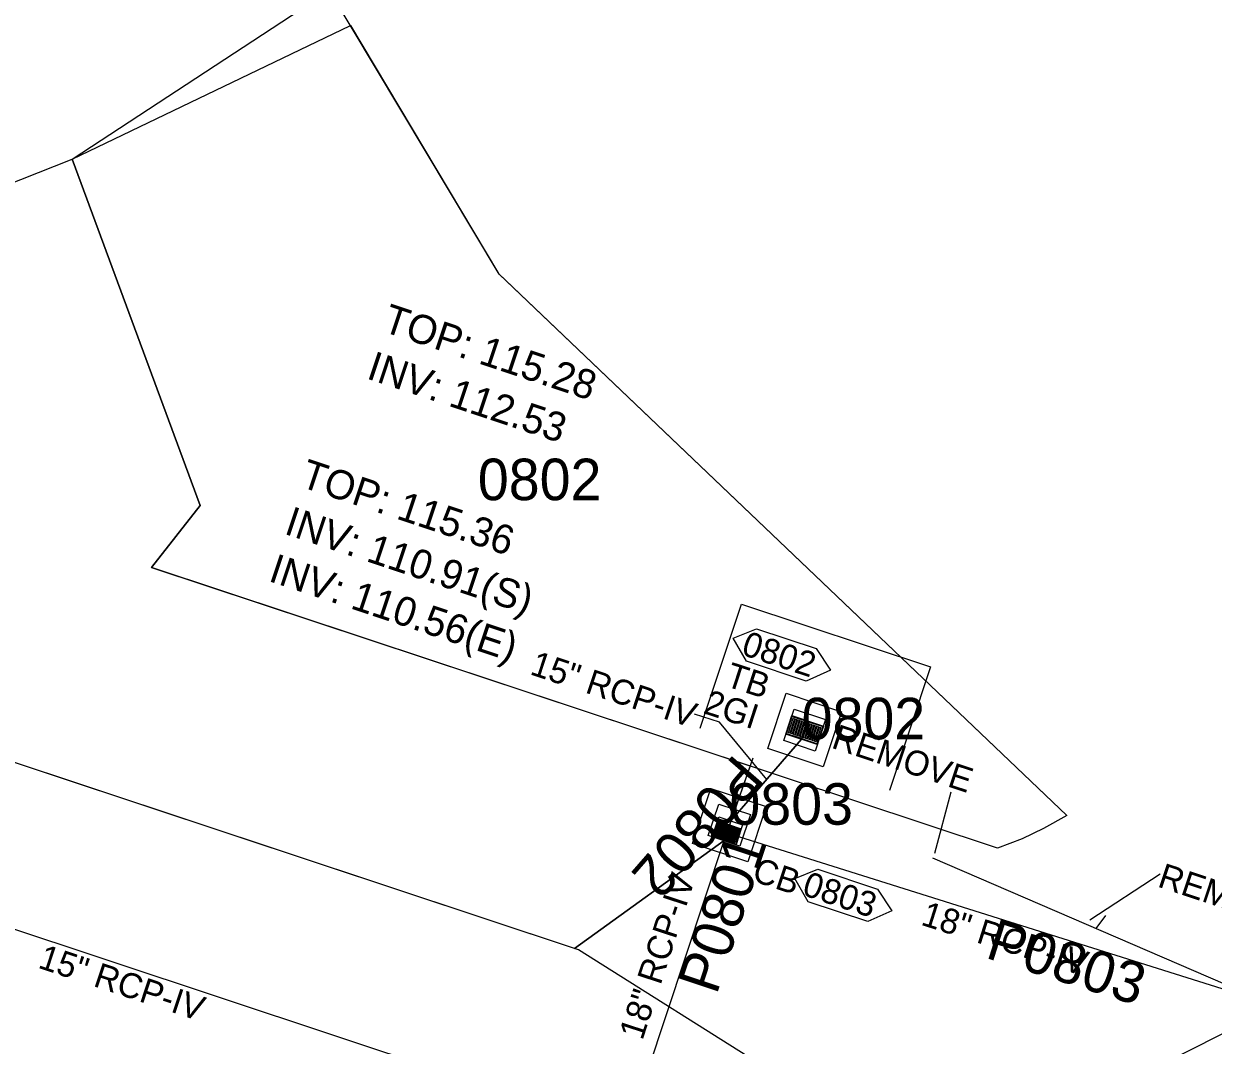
# Model space of a CAD drawing. Extents: x 2296558 to 2299313, y 599200 to 601383.
# Drawn here: x 2298959.5 to 2299102.6, y 599495.2 to 599618.1 of the extents above; entities that cross this region are included whole.
import ezdxf

# ---------------------------------------------------------------- set-up
doc = ezdxf.new("R2010")
doc.units = 0
for name, color, linetype in [('Prop Drainage Structure Box Number Symbol CELL', 7, 'Continuous'), ('Prop Drainage Structure Catch Basin Grate 840 03F Label', 7, 'Continuous'), ('Prop Drainage Structure Catch Basin Grate 840 03G CELL', 7, 'Continuous'), ('Prop Drainage Structure Catch Basin Grate 840 03G Label', 7, 'Continuous'), ('Prop Drainage Structure Drop Inlet Grate 2 Narrow Slots and Sag Grates 840 24 TB CELL', 7, 'Continuous'), ('Prop Drainage Structure Drop Inlet Grate 2 Narrow Slots and Sag Grates 840 24 TB Label', 7, 'Continuous'), ('Prop Drainage Structure Pipe RCP 15in Class IV', 7, 'Continuous'), ('Prop Drainage Structure Pipe RCP 15in Class IV Label', 7, 'Continuous'), ('Prop Drainage Structure Pipe RCP 18in Class IV', 7, 'Continuous'), ('Prop Drainage Structure Pipe RCP 18in Class IV Label', 7, 'Continuous'), ('Prop Drainage Structure Pipe Removal', 7, 'Continuous'), ('Prop Drainage Structure Plot Symbol 20 Scale', 7, 'Continuous'), ('Prop Drainage Structure Plot Symbol 50 Scale', 7, 'Continuous'), ('Prop Drainage Structure Removal Label', 7, 'Continuous'), ('Prop Drainage Structure Tops and Inverts LABEL', 7, 'Continuous'), ('Prop Plan Preparation Watershed Post Construction', 7, 'Continuous'), ('Scratch_Level_1', 7, 'Continuous'), ('Scratch_Level_3', 7, 'Continuous'), ('Scratch_Level_5', 7, 'Continuous'), ('Scratch_Level_9', 7, 'Continuous')]:
    doc.layers.add(name, color=color, linetype=linetype)

msp = doc.modelspace()

# ---------------------------------------------------------------- linework, layer by layer
at = {"layer": 'Prop Drainage Structure Box Number Symbol CELL'}
for points in [[(2299047.65, 599545.31), (2299054.83, 599542.93), (2299056.55, 599540.31), (2299053.63, 599539.02), (2299046.45, 599541.4), (2299044.85, 599544.19), (2299047.65, 599545.31)], [(2299055.05, 599516.36), (2299062.23, 599513.98), (2299063.95, 599511.36), (2299061.03, 599510.07), (2299053.85, 599512.45), (2299052.25, 599515.24), (2299055.05, 599516.36)]]:
    msp.add_lwpolyline(points, dxfattribs=at)
at = {"layer": 'Prop Drainage Structure Catch Basin Grate 840 03G CELL'}
for p, q in [((2299042.64, 599521.2), (2299042.64, 599521.2)), ((2299044.17, 599521.25), (2299042.67, 599520.52)), ((2299044.25, 599521.51), (2299042.76, 599520.79)), ((2299043.98, 599521.6), (2299042.85, 599521.05)), ((2299043.71, 599521.69), (2299042.93, 599521.31)), ((2299043.44, 599521.78), (2299043.02, 599521.57)), ((2299043.05, 599521.95), (2299043.12, 599521.98)), ((2299043.17, 599521.87), (2299043.11, 599521.84)), ((2299044.55, 599522.19), (2299044.55, 599522.19)), ((2299044.09, 599520.99), (2299042.72, 599520.33)), ((2299044, 599520.73), (2299042.99, 599520.24)), ((2299043.91, 599520.47), (2299043.26, 599520.15)), ((2299043.83, 599520.2), (2299043.53, 599520.06)), ((2299043.77, 599519.83), (2299043.77, 599519.83)), ((2299044.01, 599519.99), (2299045.37, 599520.65)), ((2299044.06, 599520.73), (2299044.06, 599520.73)), ((2299045.42, 599520.54), (2299044.06, 599519.88)), ((2299044.28, 599519.9), (2299045.28, 599520.39)), ((2299045.33, 599520.28), (2299044.33, 599519.79)), ((2299044.55, 599519.81), (2299045.19, 599520.13)), ((2299045.25, 599520.01), (2299044.6, 599519.7)), ((2299044.82, 599519.72), (2299045.1, 599519.86)), ((2299045.16, 599519.75), (2299044.87, 599519.61)), ((2299045.49, 599520.29), (2299045.49, 599520.29))]:
    msp.add_line(p, q, dxfattribs=at)
for points in [[(2299042.97, 599522.19), (2299045.82, 599521.24), (2299045.19, 599519.35), (2299042.34, 599520.29), (2299043.13, 599522.66), (2299045.97, 599521.72), (2299045.82, 599521.24)], [(2299042.98, 599522.18), (2299045.8, 599521.24), (2299045.18, 599519.36), (2299042.35, 599520.3), (2299042.98, 599522.18)], [(2299045.1, 599519.52), (2299042.51, 599520.38), (2299043.06, 599522.02), (2299045.65, 599521.16), (2299045.1, 599519.52)], [(2299042.62, 599520.64), (2299044.23, 599521.42), (2299044.17, 599521.25)], [(2299042.7, 599520.9), (2299044.19, 599521.62), (2299044.25, 599521.51)], [(2299042.79, 599521.16), (2299043.92, 599521.71), (2299043.98, 599521.6)], [(2299042.88, 599521.42), (2299043.65, 599521.8), (2299043.71, 599521.69)], [(2299042.97, 599521.69), (2299043.38, 599521.89), (2299043.44, 599521.78)], [(2299045.32, 599521.15), (2299044.07, 599520.54), (2299044.12, 599520.71), (2299045.27, 599521.26)], [(2299045.05, 599521.24), (2299044.16, 599520.8), (2299044.21, 599520.97), (2299045, 599521.35)], [(2299044.78, 599521.33), (2299044.24, 599521.07), (2299044.3, 599521.23), (2299044.73, 599521.44)], [(2299044.52, 599521.42), (2299044.33, 599521.33), (2299044.39, 599521.5), (2299044.46, 599521.53)], [(2299042.66, 599520.44), (2299044.14, 599521.16), (2299044.09, 599520.99)], [(2299042.93, 599520.35), (2299044.05, 599520.89), (2299044, 599520.73)], [(2299043.2, 599520.26), (2299043.97, 599520.63), (2299043.91, 599520.47)], [(2299043.47, 599520.17), (2299043.88, 599520.37), (2299043.83, 599520.2)], [(2299045.51, 599520.8), (2299043.9, 599520.02), (2299043.95, 599520.18), (2299045.45, 599520.91)], [(2299045.59, 599521.06), (2299043.98, 599520.28), (2299044.04, 599520.45), (2299045.54, 599521.18)]]:
    msp.add_lwpolyline(points, dxfattribs=at)
for centre, start, end in [((2299042.91, 599521.37), 115.9098, 295.9098), ((2299042.99, 599521.63), 115.9098, 295.9098), ((2299043.08, 599521.89), 115.9098, 295.9098), ((2299043.14, 599521.92), 295.9098, 115.9098), ((2299044.49, 599521.48), 295.9098, 115.9098), ((2299044.76, 599521.39), 295.9098, 115.9098), ((2299045.03, 599521.3), 295.9098, 115.9098), ((2299045.3, 599521.21), 295.9098, 115.9098), ((2299045.57, 599521.12), 295.9098, 115.9098), ((2299042.64, 599520.58), 115.9098, 295.9098), ((2299042.69, 599520.38), 115.9098, 295.9098), ((2299042.73, 599520.84), 115.9098, 295.9098), ((2299042.82, 599521.1), 115.9098, 295.9098), ((2299042.96, 599520.29), 115.9098, 295.9098), ((2299043.23, 599520.2), 115.9098, 295.9098), ((2299043.5, 599520.11), 115.9098, 295.9098), ((2299044.04, 599519.94), 115.9098, 295.9098), ((2299044.31, 599519.85), 115.9098, 295.9098), ((2299044.57, 599519.76), 115.9098, 295.9098), ((2299045.13, 599519.81), 295.9098, 115.9098), ((2299045.22, 599520.07), 295.9098, 115.9098), ((2299045.31, 599520.33), 295.9098, 115.9098), ((2299045.39, 599520.59), 295.9098, 115.9098), ((2299045.48, 599520.86), 295.9098, 115.9098), ((2299044.84, 599519.67), 115.9098, 295.9098)]:
    msp.add_arc(centre, 0.0625, start, end, dxfattribs=at)
at = {"layer": 'Prop Drainage Structure Drop Inlet Grate 2 Narrow Slots and Sag Grates 840 24 TB CELL'}
for p, q in [((2299053.81, 599534.22), (2299053.81, 599534.22)), ((2299051.55, 599533.74), (2299051.55, 599533.74)), ((2299053.44, 599533.11), (2299053.44, 599533.11)), ((2299053.08, 599532), (2299053.08, 599532)), ((2299055.34, 599532.48), (2299055.34, 599532.48))]:
    msp.add_line(p, q, dxfattribs=at)
for points in [[(2299054.97, 599531.37), (2299051.18, 599532.63), (2299051.91, 599534.85), (2299055.71, 599533.59), (2299054.97, 599531.37)], [(2299054.93, 599531.45), (2299051.26, 599532.67), (2299051.95, 599534.77), (2299055.63, 599533.55), (2299054.93, 599531.45)], [(2299053.09, 599532.08), (2299051.27, 599532.68), (2299051.96, 599534.76), (2299053.78, 599534.15), (2299053.78, 599534.15), (2299053.09, 599532.08)], [(2299051.65, 599532.75), (2299051.49, 599532.8), (2299052.06, 599534.53), (2299052.23, 599534.48), (2299051.65, 599532.75)], [(2299051.94, 599532.65), (2299051.77, 599532.71), (2299052.34, 599534.44), (2299052.51, 599534.38), (2299051.94, 599532.65)], [(2299052.22, 599532.56), (2299052.05, 599532.61), (2299052.62, 599534.34), (2299052.79, 599534.29), (2299052.22, 599532.56)], [(2299052.5, 599532.46), (2299052.33, 599532.52), (2299052.91, 599534.25), (2299053.07, 599534.19), (2299052.5, 599532.46)], [(2299052.78, 599532.37), (2299052.61, 599532.43), (2299053.19, 599534.16), (2299053.36, 599534.1), (2299052.78, 599532.37)], [(2299053.06, 599532.28), (2299052.89, 599532.33), (2299053.47, 599534.06), (2299053.64, 599534.01), (2299053.06, 599532.28)], [(2299054.93, 599531.47), (2299053.11, 599532.07), (2299053.8, 599534.15), (2299055.62, 599533.54), (2299055.62, 599533.54), (2299054.93, 599531.47)], [(2299053.42, 599532.16), (2299053.25, 599532.22), (2299053.82, 599533.95), (2299053.99, 599533.89), (2299053.42, 599532.16)], [(2299053.7, 599532.07), (2299053.53, 599532.12), (2299054.11, 599533.85), (2299054.27, 599533.8), (2299053.7, 599532.07)], [(2299053.98, 599531.97), (2299053.81, 599532.03), (2299054.39, 599533.76), (2299054.56, 599533.7), (2299053.98, 599531.97)], [(2299054.26, 599531.88), (2299054.1, 599531.93), (2299054.67, 599533.67), (2299054.84, 599533.61), (2299054.26, 599531.88)], [(2299054.55, 599531.79), (2299054.38, 599531.84), (2299054.95, 599533.57), (2299055.12, 599533.52), (2299054.55, 599531.79)], [(2299054.83, 599531.69), (2299054.66, 599531.75), (2299055.23, 599533.48), (2299055.4, 599533.42), (2299054.83, 599531.69)]]:
    msp.add_lwpolyline(points, dxfattribs=at)
at = {"layer": 'Prop Drainage Structure Pipe RCP 15in Class IV'}
for p, q in [((2298838.96, 599548.78), (2299030.68, 599485.13)), ((2299053.08, 599532), (2299044.55, 599522.19))]:
    msp.add_line(p, q, dxfattribs=at)
at = {"layer": 'Prop Drainage Structure Pipe RCP 18in Class IV'}
for p, q in [((2299032.41, 599485.61), (2299043.77, 599519.83)), ((2299045.49, 599520.29), (2299107.62, 599500.73))]:
    msp.add_line(p, q, dxfattribs=at)
at = {"layer": 'Prop Drainage Structure Pipe Removal'}
msp.add_line((2299068.84, 599517.73), (2299108.93, 599500.4), dxfattribs=at)
at = {"layer": 'Prop Drainage Structure Plot Symbol 20 Scale'}
for points in [[(2299054.71, 599530.58), (2299050.92, 599531.84), (2299052.18, 599535.64), (2299055.97, 599534.38)], [(2299045.65, 599519.15), (2299041.85, 599520.41), (2299043.11, 599524.2), (2299046.91, 599522.94)]]:
    msp.add_lwpolyline(points, close=True, dxfattribs=at)
at = {"layer": 'Prop Drainage Structure Plot Symbol 50 Scale'}
for points in [[(2299055.66, 599528.69), (2299049.02, 599530.89), (2299051.22, 599537.54), (2299057.87, 599535.33)], [(2299046.6, 599517.25), (2299039.96, 599519.46), (2299042.16, 599526.1), (2299048.8, 599523.9)]]:
    msp.add_lwpolyline(points, close=True, dxfattribs=at)
at = {"layer": 'Prop Drainage Structure Removal Label'}
for p, q in [((2299069.1, 599518.3), (2299071.06, 599525.68)), ((2299087.75, 599510.26), (2299096.25, 599515.81))]:
    msp.add_line(p, q, dxfattribs=at)
msp.add_lwpolyline([(2299048.88, 599527.17), (2299043.18, 599534.06), (2299040.19, 599535.03)], dxfattribs=at)
at = {"layer": 'Prop Plan Preparation Watershed Post Construction'}
for p, q in [((2299026.24, 599506.67), (2298828.65, 599572.25)), ((2299051.16, 599490.96), (2299026.24, 599506.67))]:
    msp.add_line(p, q, dxfattribs=at)
msp.add_lwpolyline([(2298980.69, 599560.14), (2298965.28, 599601.86), (2298998.77, 599617.93), (2299016.61, 599588.06), (2299085, 599522.85), (2299082.19, 599521.25), (2299079.62, 599520.03), (2299076.64, 599518.91), (2298974.85, 599552.7)], close=True, dxfattribs=at)
for points in [[(2298852.36, 599593.36), (2298902.13, 599576.84), (2298965.28, 599601.86), (2298980.69, 599560.14), (2298974.85, 599552.7), (2299046.88, 599528.79)], [(2299025.75, 599506.83), (2298828.65, 599572.25), (2298849.36, 599584.35), (2298852.36, 599593.36)], [(2299046.88, 599528.79), (2299043.77, 599519.83), (2299025.75, 599506.83)]]:
    msp.add_lwpolyline(points, dxfattribs=at)
at = {"layer": 'Scratch_Level_1'}
for p, q in [((2299044.55, 599522.19), (2299053.08, 599532)), ((2299088.53, 599509.24), (2299089.7, 599510.8))]:
    msp.add_line(p, q, dxfattribs=at)
for points in [[(2298902.13, 599576.84), (2298965.28, 599601.86), (2299021.46, 599638.7), (2299075.56, 599666.01)], [(2299085, 599522.85), (2299016.69, 599587.98), (2298984.08, 599642.5)], [(2299040.88, 599533.35), (2299045.84, 599548.28), (2299068.61, 599540.72), (2299063.67, 599525.82)], [(2299050.92, 599531.84), (2299052.18, 599535.64), (2299055.97, 599534.38), (2299054.71, 599530.58)], [(2299025.75, 599506.83), (2299043.77, 599519.82), (2299047.23, 599529.79)]]:
    msp.add_lwpolyline(points, dxfattribs=at)
at = {"layer": 'Scratch_Level_9'}
msp.add_line((2299055.32, 599472.12), (2299108.49, 599498.98), dxfattribs=at)

# ---------------------------------------------------------------- texts
at = {"layer": 'Prop Drainage Structure Box Number Symbol CELL'}
for s, p in [('0802', (2299045.69, 599542.24)), ('0803', (2299053, 599513.31))]:
    msp.add_text(s, height=3, rotation=341.6372, dxfattribs=at).set_placement(p)
at = {"layer": 'Prop Drainage Structure Catch Basin Grate 840 03F Label'}
msp.add_text('CB', height=3, rotation=341.6372, dxfattribs=at).set_placement((2299046.97, 599515.01))
at = {"layer": 'Prop Drainage Structure Catch Basin Grate 840 03G Label'}
for p in [(2299056.54, 599531.01), (2299095.8, 599514.3)]:
    msp.add_text('REMOVE', height=3, rotation=341.6372, dxfattribs=at).set_placement(p)
at = {"layer": 'Prop Drainage Structure Drop Inlet Grate 2 Narrow Slots and Sag Grates 840 24 TB Label'}
for s, p in [('TB', (2299043.75, 599538.46)), (' 2GI', (2299040.05, 599535.53))]:
    msp.add_text(s, height=3, rotation=341.9814, dxfattribs=at).set_placement(p)
at = {"layer": 'Prop Drainage Structure Pipe RCP 15in Class IV Label'}
for s, rotation, p in [('15" RCP-IV ', 341.6372, (2299020.26, 599539.86)), ('18" RCP-IV ', 342.4364, (2299067.31, 599509.7)), ('15" RCP-IV ', 341.6349, (2298961.05, 599504.53))]:
    msp.add_text(s, height=3, rotation=rotation, dxfattribs=at).set_placement(p)
at = {"layer": 'Prop Drainage Structure Pipe RCP 18in Class IV Label'}
msp.add_text('18" RCP-IV ', height=3, rotation=71.8905, dxfattribs=at).set_placement((2299033.91, 599495.67))
at = {"layer": 'Prop Drainage Structure Tops and Inverts LABEL'}
for s, p in [('TOP: 115.28', (2299002.47, 599581.16)), ('INV: 112.53', (2299000.58, 599575.47)), ('TOP: 115.36', (2298992.57, 599562.47)), ('INV: 110.91(S)', (2298990.67, 599556.78)), ('INV: 110.56(E)', (2298988.77, 599551.09))]:
    msp.add_text(s, height=3.5, rotation=341.5664, dxfattribs=at).set_placement(p)
at = {"layer": 'Scratch_Level_1'}
msp.add_text('0802', height=5, dxfattribs=at).set_placement((2299014.11, 599560.79))
at = {"layer": 'Scratch_Level_3'}
for s, rotation, p in [('P0802', 229.0172, (2299045.04, 599530.38)), ('P0801', 71.6371, (2299042.83, 599501.14)), ('P0803', 342.5223, (2299075.05, 599505.74))]:
    msp.add_text(s, height=5, rotation=rotation, dxfattribs=at).set_placement(p)
at = {"layer": 'Scratch_Level_5'}
for s, p in [('0802', (2299053.08, 599532)), ('0803', (2299044.39, 599521.72))]:
    msp.add_text(s, height=5, dxfattribs=at).set_placement(p)

doc.saveas('drawing.dxf')
